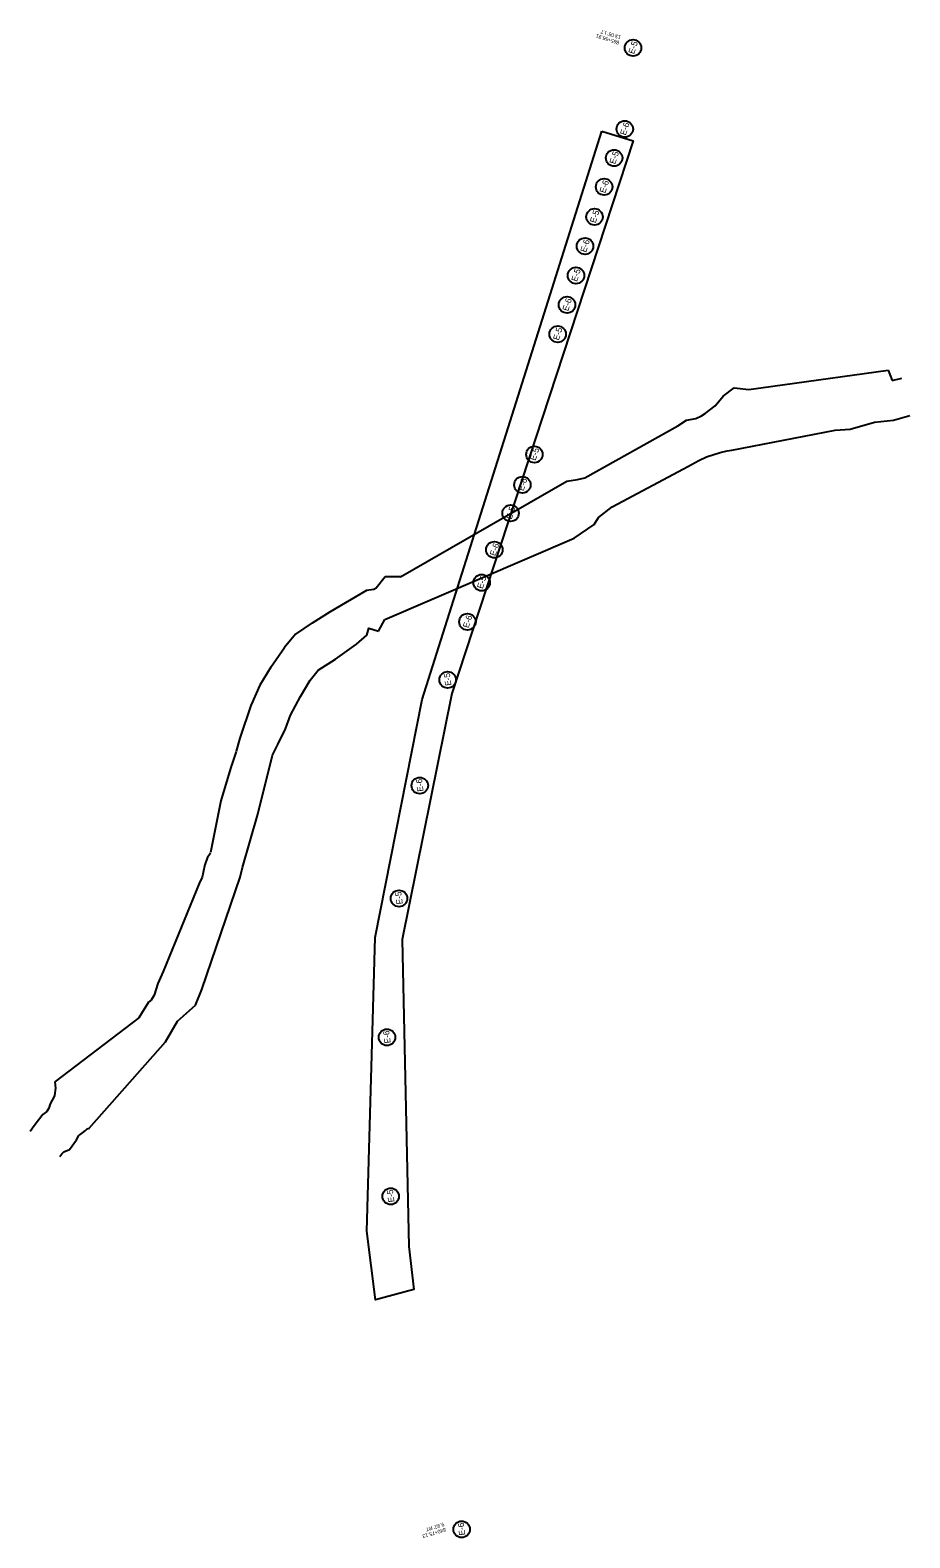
# Model space of a CAD drawing. Extents: x 641687 to 655797, y 406445 to 431088.
# Drawn here: x 643406 to 644837, y 428634 to 431088 of the extents above; entities that cross this region are included whole.
import ezdxf

# ---------------------------------------------------------------- set-up
doc = ezdxf.new("R2010")
doc.units = 0
for name, color, linetype in [('R_Erosion', 7, 'Continuous'), ('R_Erosion_Buffer', 7, 'Continuous'), ('R_No Plot', 7, 'Continuous')]:
    doc.layers.add(name, color=color, linetype=linetype)

msp = doc.modelspace()

# ---------------------------------------------------------------- linework, layer by layer
at = {"layer": 'R_Erosion'}
for centre in [(644386.8, 431059.5), (644373.4, 430927.4), (644356.1, 430880.3), (644339.8, 430833.3), (644324.1, 430784.4), (644308.7, 430736.8), (644293.9, 430689), (644279.4, 430641.2), (644264.2, 430593.5), (644226.3, 430397.7), (644206.8, 430348.3), (644187.5, 430302.1), (644161.1, 430242.6), (644140.4, 430189.1), (644117.3, 430125.3), (644085.1, 430030.8), (644039.7, 429858.7), (644005.9, 429675), (643986.3, 429449), (643992.4, 429190.1), (644107.8, 428648)]:
    msp.add_circle(centre, 13.4, dxfattribs=at)
at = {"layer": 'R_Erosion_Buffer'}
for p, q in [((644575.4, 430503.5), (644802.1, 430535.1)), ((644575.4, 430503.5), (644802.1, 430535.1)), ((644802.1, 430535.1), (644808.5, 430518.1)), ((644802.1, 430535.1), (644808.5, 430518.1)), ((644808.5, 430518.1), (644824.5, 430522.1)), ((644808.5, 430518.1), (644824.5, 430522.1)), ((644520.5, 430477.1), (644533.5, 430492.4)), ((644520.5, 430477.1), (644533.5, 430492.4)), ((644533.5, 430492.4), (644551.4, 430506)), ((644533.5, 430492.4), (644551.4, 430506)), ((644551.4, 430506), (644575.4, 430503.5)), ((644551.4, 430506), (644575.4, 430503.5)), ((644489.3, 430456.4), (644498.2, 430460.4)), ((644489.3, 430456.4), (644498.2, 430460.4)), ((644498.2, 430460.4), (644504, 430464.2)), ((644498.2, 430460.4), (644504, 430464.2)), ((644504, 430464.2), (644520.5, 430477.1)), ((644504, 430464.2), (644520.5, 430477.1)), ((644811, 430453.7), (644837.4, 430461.1)), ((644811, 430453.7), (644837.4, 430461.1)), ((644308.2, 430359.8), (644459.8, 430444.2)), ((644308.2, 430359.8), (644459.8, 430444.2)), ((644459.8, 430444.2), (644474.1, 430453.7)), ((644459.8, 430444.2), (644474.1, 430453.7)), ((644474.1, 430453.7), (644489.3, 430456.4)), ((644474.1, 430453.7), (644489.3, 430456.4)), ((644547.6, 430404.6), (644716, 430437.4)), ((644547.6, 430404.6), (644716, 430437.4)), ((644716, 430437.4), (644740.5, 430439.1)), ((644716, 430437.4), (644740.5, 430439.1)), ((644740.5, 430439.1), (644779.6, 430450.3)), ((644740.5, 430439.1), (644779.6, 430450.3)), ((644779.6, 430450.3), (644811, 430453.7)), ((644779.6, 430450.3), (644811, 430453.7)), ((644482, 430381.2), (644494, 430387.6)), ((644482, 430381.2), (644494, 430387.6)), ((644494, 430387.6), (644506.5, 430393.6)), ((644494, 430387.6), (644506.5, 430393.6)), ((644506.5, 430393.6), (644528.7, 430400.7)), ((644506.5, 430393.6), (644528.7, 430400.7)), ((644528.7, 430400.7), (644539.8, 430403.6)), ((644528.7, 430400.7), (644539.8, 430403.6)), ((644539.8, 430403.6), (644547.6, 430404.6)), ((644539.8, 430403.6), (644547.6, 430404.6)), ((644353, 430312.2), (644477.1, 430378.5)), ((644353, 430312.2), (644477.1, 430378.5)), ((644477.1, 430378.5), (644482, 430381.2)), ((644477.1, 430378.5), (644482, 430381.2)), ((644008.6, 430198.6), (644279.3, 430354.1)), ((644008.6, 430198.6), (644279.3, 430354.1)), ((644279.3, 430354.1), (644296.4, 430356.7)), ((644279.3, 430354.1), (644296.4, 430356.7)), ((644296.4, 430356.7), (644308.2, 430359.8)), ((644296.4, 430356.7), (644308.2, 430359.8)), ((644330.7, 430294.9), (644353, 430312.2)), ((644330.7, 430294.9), (644353, 430312.2)), ((644323.3, 430283.7), (644330.7, 430294.9)), ((644323.3, 430283.7), (644330.7, 430294.9)), ((644291.2, 430261.5), (644323.3, 430283.7)), ((644291.2, 430261.5), (644323.3, 430283.7)), ((643983, 430129), (644291.2, 430261.5)), ((643983, 430129), (644291.2, 430261.5)), ((643983.6, 430198.4), (643968.6, 430179.9)), ((643983.6, 430198.4), (643968.6, 430179.9)), ((644008.6, 430198.6), (643983.6, 430198.4)), ((644008.6, 430198.6), (643983.6, 430198.4)), ((643953, 430176.5), (643894.1, 430141.8)), ((643953, 430176.5), (643894.1, 430141.8)), ((643965.2, 430177.8), (643953, 430176.5)), ((643965.2, 430177.8), (643953, 430176.5)), ((643968.6, 430179.9), (643965.2, 430177.8)), ((643968.6, 430179.9), (643965.2, 430177.8)), ((643894.1, 430141.8), (643864.7, 430123.3)), ((643894.1, 430141.8), (643864.7, 430123.3)), ((643864.7, 430123.4), (643837.6, 430105)), ((643864.7, 430123.4), (643837.6, 430105)), ((643972.4, 430110.2), (643983, 430129)), ((643972.4, 430110.2), (643983, 430129)), ((643837.6, 430105), (643819.1, 430083)), ((643837.6, 430105), (643819.1, 430083)), ((643819.3, 430083.2), (643797.4, 430051.1)), ((643819.3, 430083.2), (643797.4, 430051.1)), ((643902.5, 430064.5), (643936.9, 430088.7)), ((643902.5, 430064.5), (643936.9, 430088.7)), ((643797.5, 430051.2), (643779.6, 430022.1)), ((643797.5, 430051.2), (643779.6, 430022.1)), ((643861.1, 430030.3), (643874.4, 430046.8)), ((643861.1, 430030.3), (643874.4, 430046.8)), ((643874.4, 430046.8), (643902.5, 430064.5)), ((643874.4, 430046.8), (643902.5, 430064.5)), ((643779.6, 430022.1), (643765, 429990.3)), ((643779.6, 430022.1), (643765, 429990.3)), ((643845.6, 430003.8), (643861.1, 430030.3)), ((643845.6, 430003.8), (643861.1, 430030.3)), ((643829.5, 429973.1), (643845.6, 430003.8)), ((643829.5, 429973.1), (643845.6, 430003.8)), ((643765, 429990.5), (643746.7, 429935.7)), ((643765, 429990.5), (643746.7, 429935.7)), ((643820.9, 429951.3), (643829.5, 429973.1)), ((643820.9, 429951.3), (643829.5, 429973.1)), ((643808.9, 429925.5), (643820.9, 429951.3)), ((643808.9, 429925.5), (643820.9, 429951.3)), ((643746.7, 429935.8), (643741.1, 429914.5)), ((643746.7, 429935.8), (643741.1, 429914.5)), ((643800.2, 429908.1), (643808.9, 429925.5)), ((643800.2, 429908.1), (643808.9, 429925.5)), ((643741, 429914.4), (643733.4, 429891.6)), ((643741, 429914.4), (643733.4, 429891.6)), ((643775.9, 429812.4), (643800.2, 429908.1)), ((643775.9, 429812.4), (643800.2, 429908.1)), ((643733.4, 429891.7), (643716.1, 429833.8)), ((643733.4, 429891.7), (643716.1, 429833.8)), ((643716.1, 429834), (643699.2, 429749.6)), ((643716.1, 429834), (643699.2, 429749.6)), ((643751, 429725.6), (643775.9, 429812.4)), ((643751, 429725.6), (643775.9, 429812.4)), ((643698.9, 429748.9), (643694, 429741.7)), ((643698.9, 429748.9), (643694, 429741.7)), ((643689.8, 429730.2), (643687, 429717.3)), ((643689.8, 429730.2), (643687, 429717.3)), ((643694.2, 429742.2), (643689.7, 429729.9)), ((643694.2, 429742.2), (643689.7, 429729.9)), ((643747.2, 429709.7), (643751, 429725.6)), ((643747.2, 429709.7), (643751, 429725.6)), ((643680.6, 429699.3), (643622.1, 429556.1)), ((643680.6, 429699.3), (643622.1, 429556.1)), ((643685.3, 429709.5), (643680.6, 429699.3)), ((643685.3, 429709.5), (643680.6, 429699.3)), ((643685.2, 429526.8), (643747.2, 429709.7)), ((643685.2, 429526.8), (643747.2, 429709.7)), ((643687, 429717.3), (643685.4, 429709.9)), ((643687, 429717.3), (643685.4, 429709.9)), ((643622.1, 429556.1), (643613.2, 429536.5)), ((643622.1, 429556.1), (643613.2, 429536.5)), ((643613.2, 429536.5), (643607.2, 429517.5)), ((643613.2, 429536.5), (643607.2, 429517.5)), ((643598.2, 429506.2), (643582.2, 429480.6)), ((643598.2, 429506.2), (643582.2, 429480.6)), ((643602.3, 429509.3), (643598.2, 429506.2)), ((643602.3, 429509.3), (643598.2, 429506.2)), ((643607.2, 429517.5), (643602.3, 429509.3)), ((643607.2, 429517.5), (643602.3, 429509.3)), ((643674.9, 429501.5), (643685.2, 429526.8)), ((643674.9, 429501.5), (643685.2, 429526.8)), ((643582.2, 429480.6), (643445.9, 429376.6)), ((643582.2, 429480.6), (643445.9, 429376.6)), ((643645.4, 429475.2), (643674.9, 429501.5)), ((643645.4, 429475.2), (643674.9, 429501.5)), ((643625.8, 429441.4), (643645.4, 429475.2)), ((643625.8, 429441.4), (643645.4, 429475.2)), ((643501.7, 429301.2), (643625.8, 429441.4)), ((643501.7, 429301.2), (643625.8, 429441.4)), ((643446.8, 429366), (643445.2, 429354.3)), ((643446.8, 429366), (643445.2, 429354.3)), ((643445.9, 429376.6), (643446.8, 429366)), ((643445.9, 429376.6), (643446.8, 429366)), ((643435.7, 429333.4), (643432.6, 429328.2)), ((643435.7, 429333.4), (643432.6, 429328.2)), ((643438.3, 429340.7), (643435.7, 429333.4)), ((643438.3, 429340.7), (643435.7, 429333.4)), ((643444.5, 429352.8), (643438.3, 429340.7)), ((643444.5, 429352.8), (643438.3, 429340.7)), ((643445.2, 429354.3), (643444.5, 429352.8)), ((643445.2, 429354.3), (643444.5, 429352.8)), ((643426, 429323.1), (643412.1, 429304.9)), ((643426, 429323.1), (643412.1, 429304.9)), ((643432.6, 429328.2), (643426, 429323.1)), ((643432.6, 429328.2), (643426, 429323.1)), ((643412.1, 429304.9), (643405.5, 429295.8)), ((643412.1, 429304.9), (643405.5, 429295.8)), ((643469.6, 429266.6), (643481.1, 429282.1)), ((643469.6, 429266.6), (643481.1, 429282.1)), ((643481.1, 429282.1), (643485, 429288.9)), ((643481.1, 429282.1), (643485, 429288.9)), ((643485, 429288.9), (643486.6, 429290.4)), ((643485, 429288.9), (643486.6, 429290.4)), ((643486.6, 429290.4), (643490.5, 429293.6)), ((643486.6, 429290.4), (643490.5, 429293.6)), ((643490.5, 429293.6), (643495.4, 429297.2)), ((643490.5, 429293.6), (643495.4, 429297.2)), ((643495.4, 429297.2), (643498.5, 429299.9)), ((643495.4, 429297.2), (643498.5, 429299.9)), ((643498.5, 429299.9), (643501.7, 429301.2)), ((643498.5, 429299.9), (643501.7, 429301.2)), ((643453.7, 429254.8), (643456.9, 429259.2)), ((643453.7, 429254.8), (643456.9, 429259.2)), ((643456.9, 429259.2), (643460.1, 429262.5)), ((643456.9, 429259.2), (643460.1, 429262.5)), ((643460.1, 429262.5), (643469.6, 429266.6)), ((643460.1, 429262.5), (643469.6, 429266.6))]:
    msp.add_line(p, q, dxfattribs=at)
msp.add_lwpolyline([(643936.9, 430088.7), (643953.4, 430103.6), (643957, 430115), (643972.4, 430110.2)], dxfattribs=at)
msp.add_lwpolyline([(643936.9, 430088.7), (643953.4, 430103.6), (643957, 430115), (643972.4, 430110.2)], dxfattribs=at)
at = {"layer": 'R_No Plot'}
msp.add_lwpolyline([(644336.2, 430923.9), (644387, 430908.4), (644091.8, 430008.5), (644010.8, 429608.2), (644021.8, 429108.5), (644030.1, 429038.3), (643967.7, 429021.6), (643953.4, 429133.2), (643967.1, 429611.4), (644043.6, 429998.9), (644183.7, 430440.8), (644336.2, 430923.9)], dxfattribs=at)

# ---------------------------------------------------------------- texts
at = {"layer": 'R_Erosion'}
for s, rotation, p in [('E-5', 72.1351, (644388.5, 431048.7)), ('E-6', 72.1351, (644375, 430916.5)), ('E-5', 72.1351, (644357.7, 430869.5)), ('E-6', 72.1351, (644341.5, 430822.3)), ('E-5', 72.1351, (644325.8, 430773.6)), ('E-6', 72.1351, (644310.3, 430725.9)), ('E-5', 72.1351, (644295.6, 430678.3)), ('E-6', 72.1351, (644281.1, 430630.3)), ('E-5', 72.1351, (644265.9, 430582.7)), ('E-5', 72.1351, (644228, 430386.9)), ('E-6', 72.1351, (644208.5, 430337.4)), ('E-5', 72.1351, (644189.2, 430291.3)), ('E-6', 72.1351, (644162.8, 430231.7)), ('E-5', 72.1351, (644142.1, 430178.3)), ('E-6', 72.1351, (644119, 430114.4)), ('E-5', 97.2205, (644091.2, 430021.8)), ('E-6', 97.2205, (644045.8, 429849.5)), ('E-5', 97.2205, (644012, 429666)), ('E-6', 97.2205, (643992.4, 429439.8)), ('E-5', 97.2205, (643998.5, 429181)), ('E-6', 97.2205, (644113.9, 428638.8))]:
    msp.add_text(s, height=10, rotation=rotation, dxfattribs=at).set_placement(p)
at = {"layer": 'R_No Plot'}
for s, rotation, p in [('865+56.91 ', 162.5201, (644365, 431070.4)), ("13.05' LT  ", 162.5201, (644367.7, 431079)), ('840+75.13 ', 196.661, (644081.2, 428650.6)), ("9.92' RT  ", 196.661, (644078.6, 428659.2))]:
    msp.add_text(s, height=6, rotation=rotation, dxfattribs=at).set_placement(p)

doc.saveas('drawing.dxf')
